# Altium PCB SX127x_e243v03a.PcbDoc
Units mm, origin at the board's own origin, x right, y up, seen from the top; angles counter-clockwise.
Board outline 56 x 36 mm, 2 copper layers (Top Layer, Bottom Layer), stack 1.6 mm thick; 60 components, 66 nets, 205 pads, 400 vias.
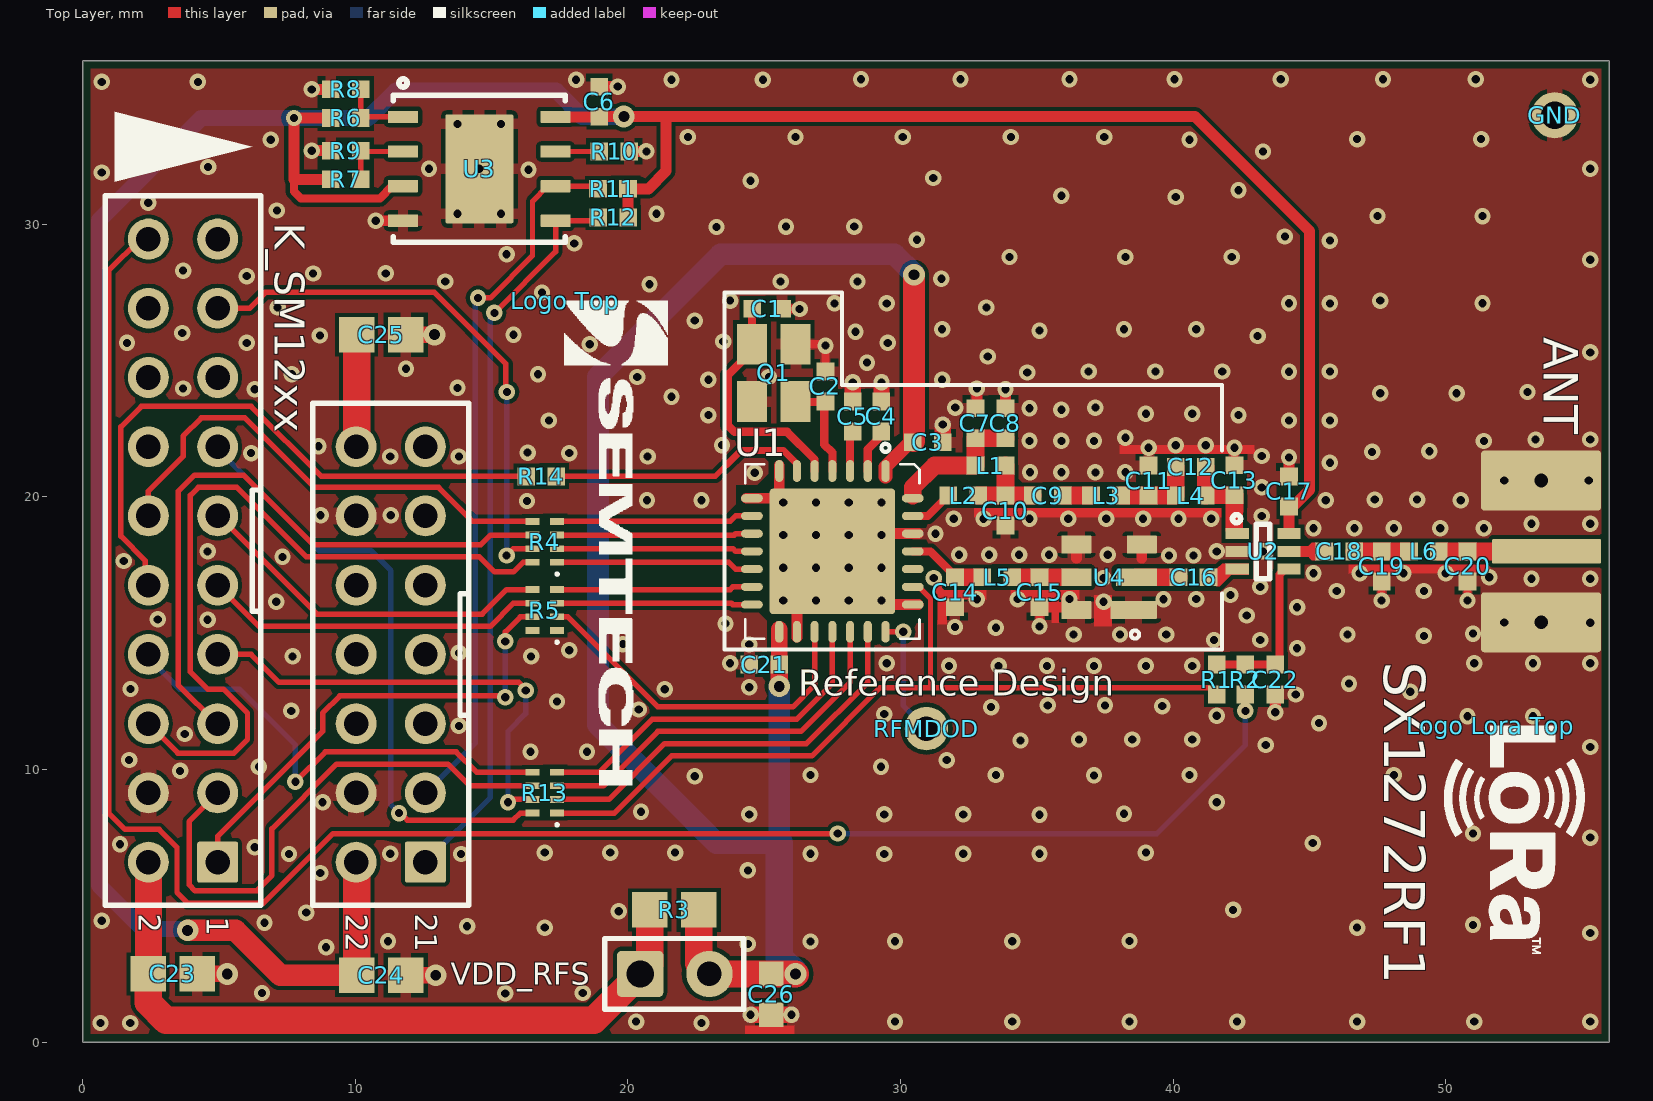
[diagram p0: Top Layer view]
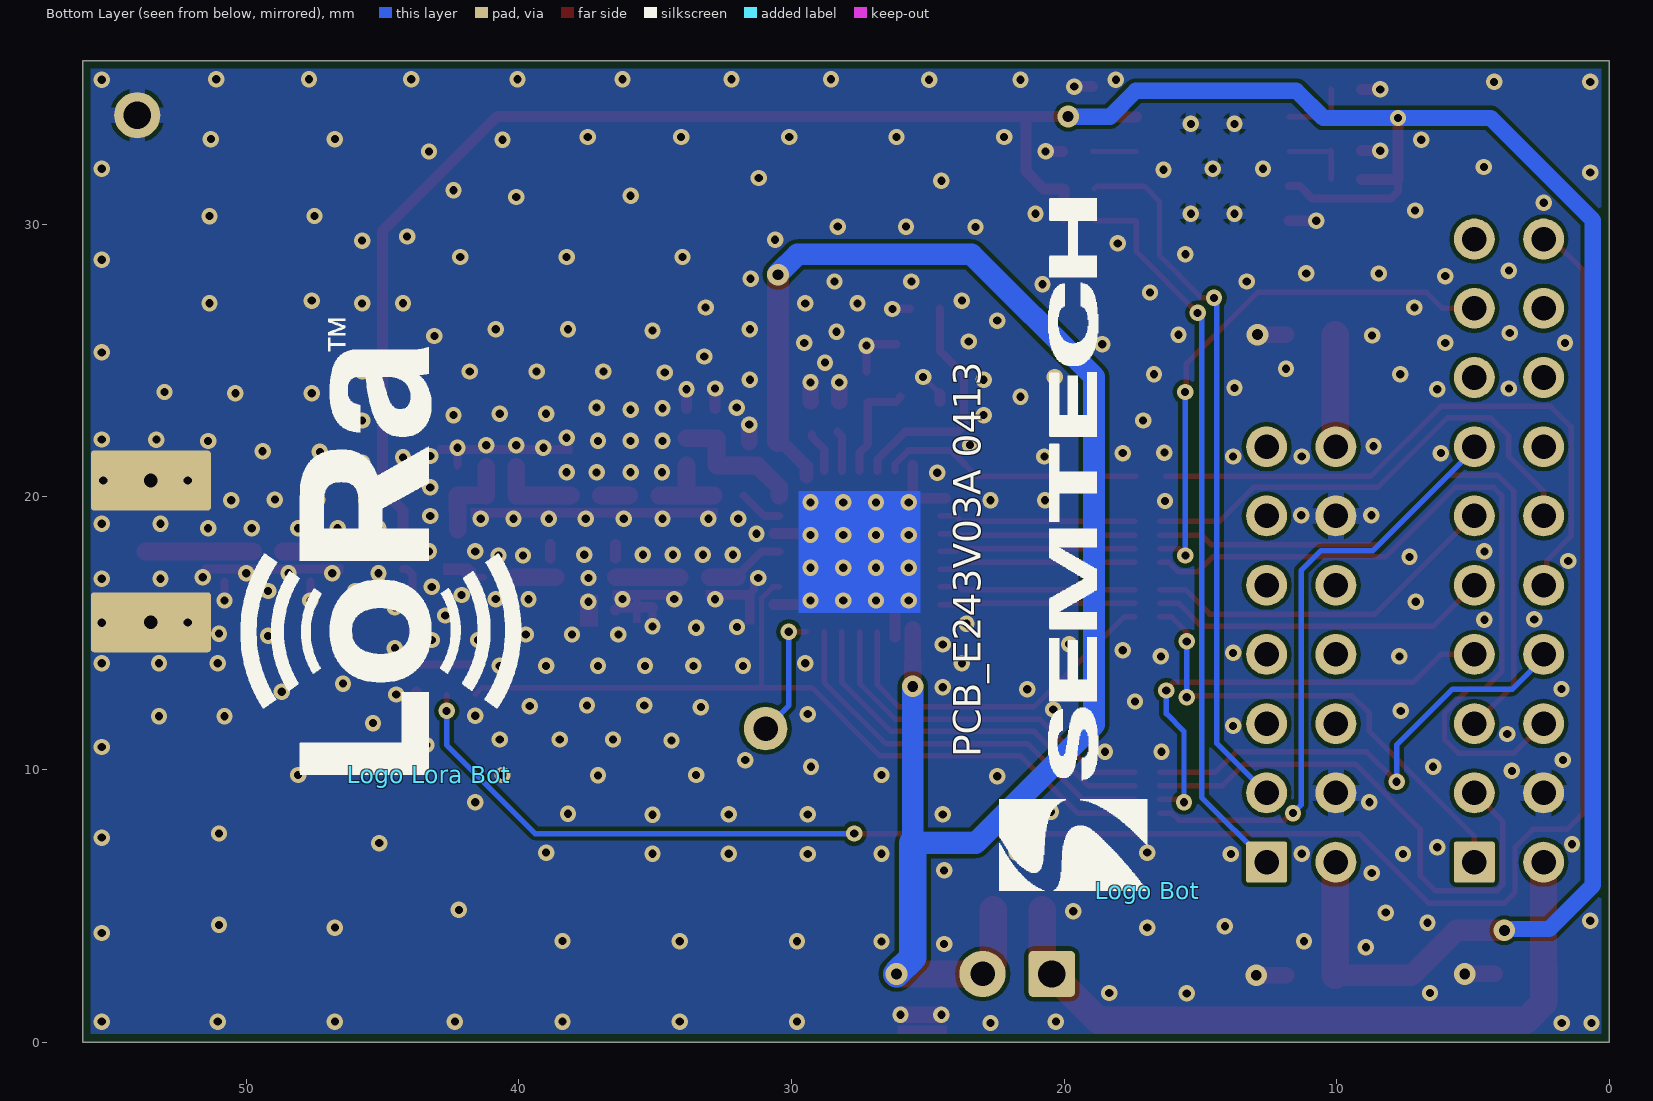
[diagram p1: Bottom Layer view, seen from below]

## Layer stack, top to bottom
Top Layer: signal copper 0.035
Dielectric: core 1.53, FR-4, Dk 4.2
Bottom Layer: signal copper 0.035

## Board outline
0,0 0,36 56,36 56,0

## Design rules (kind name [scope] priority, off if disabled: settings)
Clearance Clearance_GND [InNet('GND')] p1: gap=0.15
Clearance [All] p2: gap=0.15
ComponentClearance ComponentClearance_keepout ['SX1232LR_e243v01a' vs OnLayer('Mechanical 12')] p1: gap=0.25 collisioncheckmode=3 verticalgap=0.3 showdistances=FALSE
ComponentClearance [All] p2: gap=0.25 collisioncheckmode=3 verticalgap=0.3 showdistances=FALSE
HoleSize [All] p1: absolutevalues=TRUE maxlimit=3.6 minlimit=0.25 maxpercent=80.000 minpercent=20.000
HoleToHoleClearance [All] p1: gap=0.25 allowstackedmicrovias=TRUE
MinimumSolderMaskSliver [All] p1: minsoldermaskwidth=0.05
PlaneClearance [All] p1: clearance=0.2
PlaneConnect [All] p1: planeconnectstyle=Direct reliefexpansion=0.508 reliefentries=4 reliefconductorwidth=0.254 reliefairgap=0.254
PolygonConnect "PolygonConnect SAW_DCC6C" [InNet('GND') vs HasFootprint('DCC6C_3.0x3.0mm')] p1: connectstyle=Relief reliefconductorwidth=0.65 reliefentries=4 polygonreliefangle="90 Angle"
PolygonConnect "PolygonConnect SMD" [InNet('GND') vs HasFootprint('nd3225da - nd2520da') or HasFootprint('DD10_L') or HasFootprint('MSOP8')  or  HasFootprint('vqfn28_6x6mm') or HasFootprint('SOIC-SN8_L')  or HasFootprint('rlc_1206_smd capa pol') or HasFootprint('rlc_603_smd') or HasFootprint('rlc_402_smd') or HasFootprint('rlc_402_smd diode') or hasFootprint('rlc_805_smd') or HasFootprint('rlc_1210_smd')   or HasFootprint('MiniMold-6') or HasFootprint('DFN8_ 5x6mm')] p2: connectstyle=Relief reliefconductorwidth=0.4 reliefentries=4 polygonreliefangle="90 Angle"
PolygonConnect PolygonConnect_comp_diverse [InNet('GND') vs HasFootprint('CD1608-0603') or  HasFootprint('HDR34 Header') or  HasFootprint('BRIDGE_254MM') or  HasFootprint('pin_1mm') or HasFootprint('SMA_END_LAUNCH_JACK_RECEPTACLE')] p3: connectstyle=Relief reliefconductorwidth=0.6 reliefentries=4 polygonreliefangle="90 Angle"
PolygonConnect PolygonConnect_all [All] p4: connectstyle=Direct reliefconductorwidth=0.6 reliefentries=4 polygonreliefangle="90 Angle"
RoomDefinition SX127x_e243v03a [InComponentClass('SX127x_e243v03a')] p1: confinementstyle=ConfineOut formatcopy=TRUE lockcomponents=FALSE outline 62.449,-0.9 62.449,6.1 67.709,6.1 67.709,-0.9
RoutingVias [All] p1: holewidth=0.3 width=0.6 viastyle="Through Hole" minholewidth=0.25 minwidth=0.5 maxholewidth=0.4 maxwidth=0.8
SilkToSilkClearance [All] p1: silktosilkclearance=0.05
SilkscreenOverComponentPads [All] p1: minsilkscreentomaskgap=0.05
SolderMaskExpansion [All] p1: expansion=0.05
Width "Width GND" [InNet('GND')] p1: maxlimit=3 minlimit=0.2 preferedwidth=0.4
Width Width_VCC [InNet('VDD_RF') or  InNet('VDD_RFS') or  InNet('VCC') or  InNet('VBAT') or InNet('VSUPERCAP') or InNet('VCC_FEM')   or InNet('VCC_PA')] p2: maxlimit=2 minlimit=0.2 preferedwidth=0.8
Width "Width All" [All] p3: maxlimit=2 minlimit=0.15 preferedwidth=0.2
20 further rules are at their usual default settings.

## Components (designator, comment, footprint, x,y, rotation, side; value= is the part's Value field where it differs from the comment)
ANT "SMA" "SMA END LAUNCH JACK RECEPTACLE SHORT" 53.7,18 r90 top locked
C1 "Cap" rlc_402_smd 25.11,26.904 r180 top
C2 "Cap" rlc_402_smd 27.248,24.05 r270 top
C3 "Cap" rlc_402_smd 31,22 r180 top
C4 "Cap" rlc_402_smd 29.295,22.95 r270 top
C5 "Cap" rlc_402_smd 28.25,22.95 r270 top
C6 "Cap" rlc_402_smd 18.949,34.5 r270 top
C7 "Cap" rlc_402_smd 32.75,22.7 r270 top
C8 "Cap" rlc_402_smd 33.85,22.7 r270 top
C9 "Cap" rlc_402_smd 35.4,20.05 r180 top
C10 "Cap" rlc_402_smd 33.85,19.5 r90 top
C11 "Cap" rlc_402_smd 39.1,20.6 r270 top
C12 "Cap" rlc_402_smd 40.65,21.1 r180 top
C13 "Cap" rlc_402_smd 42.249,20.61 r270 top
C14 "Cap" rlc_402_smd 32,16.5 r90 top
C15 "Cap" rlc_402_smd 35.1,16.5 r90 top
C16 "Cap" rlc_402_smd 40.75,17.05 r180 top
C17 "Cap" rlc_402_smd 44.252,20.2 r270 top
C18 "Cap" rlc_402_smd 46.1,18 r180 top
C19 "Cap" rlc_402_smd 47.65,17.45 r90 top
C20 "Cap" rlc_402_smd 50.8,17.45 r90 top
C21 "Cap" rlc_402_smd 25,13.85 r0 top
C22 "Cap" rlc_402_smd 43.749,13.3 r270 top
C23 "Cap" rlc_805_smd 3.299,2.5 r180 top
C24 "Cap" rlc_805_smd 10.949,2.45 r180 top
C25 "Cap" rlc_805_smd 10.949,25.95 r0 top
C26 "Cap Semi" rlc_603_smd 25.25,1.75 r90 top
GND "Test Pin" pin_1mm 54,34 r0 top
K_SM12xx "SM12xx Header" "HDR34 Header" 4.95,6.6 r90 top locked
L1 "Inductor" rlc_402_smd 33.3,21.15 r180 top
L2 "Inductor" rlc_402_smd 32.3,20.05 r0 top
L3 "Inductor" rlc_402_smd 37.54,20.05 r0 top
L4 "Inductor" rlc_402_smd 40.65,20.05 r0 top
L5 "Inductor" rlc_402_smd 33.55,17.05 r0 top
L6 "Inductor" rlc_402_smd 49.2,18 r0 top
"Logo Bot" "Logo symbol" logo_semtech_horiz_size3 16.95,5.55 r90 bottom
"Logo Lora Bot" "Logo symbol" "Logo LoRa Size4" 43.3,9.8 r90 bottom
"Logo Lora Top" "Logo symbol" "Logo LoRa Size2" 51.65,11.6 r270 top
"Logo Top" "Logo symbol" logo_semtech_horiz_size2 17.7,27.2 r270 top
Q1 "Xtal" "ND3225DA - ND2520DA" 25.35,24.551 r270 top
R1 "Resistor" rlc_402_smd 41.6,13.3 r90 top
R2 "Resistor" rlc_402_smd 42.649,13.3 r270 top
R3 "Resistor" rlc_805_smd 21.7,4.85 r180 top
R4 "EXBN8VxxxJX" EXB28V 16.95,18.35 r90 top
R5 "EXBN8VxxxJX" EXB28V 16.95,15.85 r90 top
R6 "Resistor" rlc_402_smd 9.649,33.9 r180 top
R7 "Resistor" rlc_402_smd 9.649,31.65 r180 top
R8 "Resistor" rlc_402_smd 9.649,34.95 r0 top
R9 "Resistor" rlc_402_smd 9.649,32.7 r0 top
R10 "Resistor" rlc_402_smd 19.499,32.674 r180 top
R11 "Resistor" rlc_402_smd 19.45,31.3 r0 top
R12 "Resistor" rlc_402_smd 19.457,30.25 r0 top
R13 "EXBN8VxxxJX" EXB28V 16.95,9.15 r90 top
R14 "Resistor" rlc_402_smd 16.821,20.75 r180 top
RFMDOD "Test Pin" pin_0.9mm 30.95,12 r90 top
U1 "SX1272" vqfn28_6x6mm 27.5,18 r270 top
U2 "RF Switch" SC70-6 43.3,18 r0 top
U3 "24AA128-I/MF" "DFN8_ 5x6mm" 14.549,32.035 r270 top
U4 "SAW Filter" DCC6C_3.0X3.0MM 37.65,17.05 r180 top
VDD_RFS "Jumper" BRIDGE_254MM 20.45,2.5 r0 top

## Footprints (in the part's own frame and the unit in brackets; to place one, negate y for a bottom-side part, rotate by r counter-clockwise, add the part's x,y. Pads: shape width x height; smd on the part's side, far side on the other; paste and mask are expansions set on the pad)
BRIDGE_254MM [mm] "Generic Bridge 2.54mm, 2 Leads 0.9mm;"
  rrect20% 1.7x1.7 hole 1 paste+0 mask+0.05: 1(0,0)
  round 1.7 hole 0.9 paste+0 mask+0.05: 2(2.54,0)
  silkscreen extent -1.3,-1.3 3.8,1.3, body extent -1.4,-1.4 3.9,1.4, height 1
DCC6C_3.0X3.0MM [mm] "DCC6C footprint, 3.0x3.0mm"
  rrect5% 1.7x0.65 smd mask+0.05: 1(-0.9,1.2)
  rrect5% 1.5x0.65 smd mask+0.05: 2(-1,0)
  rrect5% 1.1x0.65 smd mask+0.05: 3(-1.2,-1.2) 4(1.2,-1.2) 5(1.2,0) 6(1.2,1.2)
  silkscreen extent -1.1,1.95 -0.8,2.25, body extent -1.5,-1.5 1.5,1.5, height 1
"DFN8_ 5x6mm" [mm] "8 Leads, Body 5x6mm, pitch 1.27mm, DFN8"
  rrect10% 0.45x1.1 smd paste+0 mask+0.05: 1(-1.905,-2.8) 2(-0.635,-2.8) 3(0.635,-2.8) 4(1.905,-2.8) 5(1.905,2.8) 6(0.635,2.8) 7(-0.635,2.8) 8(-1.905,2.8)
  rrect5% 4x2.5 smd paste+0 mask+0.05: 9(0,0)
  silkscreen extent -3.3,-3.15 2.7,3.15, body extent -2.5,-3 2.5,3, height 12
EXB28V [mm] "Chip Resistor Array, (0402x4); SM; 8 Leads; Body 2.10 x 1.10 mm (LxW max)"
  rect 0.25x0.5 smd: 1(-0.75,-0.45) 2(-0.25,-0.45) 3(0.25,-0.45) 4(0.75,-0.45) 5(0.75,0.45) 6(0.25,0.45) 7(-0.25,0.45) 8(-0.75,0.45)
  silkscreen extent -1.23,-0.5 -1.13,-0.4
"HDR34 Header" [mm] "Connector; Header; 34 Position - SM12xx Header"
  rrect10% 1.5x1.5 hole 0.9 mask+0.05: 1(0,0) 21(0,-7.62)
  round 1.5 hole 0.9 mask+0.05: 2(0,2.54) 3(2.54,0) 4(2.54,2.54) 5(5.08,0) 6(5.08,2.54) 7(7.62,0) 8(7.62,2.54) 9(10.16,0) 10(10.16,2.54) 11(12.7,0) 12(12.7,2.54) 13(15.24,0) 14(15.24,2.54) 15(17.78,0) 16(17.78,2.54) 17(20.32,0) 18(20.32,2.54) 19(22.86,0) 20(22.86,2.54) 22(0,-5.08) 23(2.54,-7.62) 24(2.54,-5.08) 25(5.08,-7.62) 26(5.08,-5.08) 27(7.62,-7.62) 28(7.62,-5.08) 29(10.16,-7.62) 30(10.16,-5.08) 31(12.7,-7.62) 32(12.7,-5.08) 33(15.24,-7.62) 34(15.24,-5.08)
  silkscreen extent -1.59,-9.21 27.53,4.13, body extent -1.59,-9.21 24.45,4.13
"Logo LoRa Size2" [mm]
  silkscreen extent 0,-1.69 8.37,3.44
"Logo LoRa Size4" [mm] "Logo LoRa Size4 - Top Overlay"
  silkscreen extent 0,-3.38 16.73,6.89
logo_semtech_horiz_size2 [mm] "Logo semtech horizontal - size2 - M"
  silkscreen extent 0,-0.03 17.78,3.76, body extent 0,0 0.08,0, height 6
logo_semtech_horiz_size3 [mm] "Logo semtech horizontal - size3 - L"
  silkscreen extent 0,0 25.4,5.41, body extent -0.01,-0.01 25.41,5.42
"ND3225DA - ND2520DA" [mm] "Crystal SMD 3.2x2.5mm compatible with 2.5x2.0mm"
  rect 1.5x1.1 smd mask+0.05: 1(-1.05,-0.8) 2(1.05,-0.8) 3(1.05,0.8) 4(-1.05,0.8)
  body extent -1.6,-1.25 1.6,1.25, height 1
pin_0.9mm [mm] "Generic Pin 0.9mm; 1 Lead"
  round 1.6 hole 0.9 mask+0.05: 1(-0.5,0)
pin_1mm [mm] "Generic Pin 1.1mm; 1 Lead"
  round 1.7 hole 1 paste+0 mask+0.05: 1(0,0)
rlc_402_smd [mm] "Chip SMD component 402; Body 1.0 x 0.5 mm (LxW typ)"
  rect 0.65x0.65 smd mask+0.05: 1(-0.55,0) 2(0.55,0)
rlc_603_smd [mm] "Chip SMD component 603; Body 1.6 x 0.8mm (LxW typ)"
  rect 0.9x0.9 smd paste+0 mask+0.05: 1(-0.75,0) 2(0.75,0)
rlc_805_smd [mm] "Chip SMD component 805; Body 2.0 x 1.25 mm (LxW typ)"
  rect 1.3x1.3 smd mask+0.05: 1(-0.9,0) 2(0.9,0)
SC70-6 [mm] "SC70 6-Leads, Body 2.0x1.25mm, Pitch 0.65mm"
  rect 0.85x0.4 smd mask+0.05: 1(-0.95,0.65) 2(-0.95,0) 3(-0.95,-0.65) 4(0.95,-0.65) 5(0.95,0) 6(0.95,0.65)
  silkscreen extent -1.12,-1 0.25,1.35, body extent -0.63,-1 0.63,1, height 1.45
"SMA END LAUNCH JACK RECEPTACLE SHORT" [mm] "SMA Connector - End Launch Jack Receptacle - Short"
  rrect10% 0.9x4 smd paste+0 mask+0.05: 1(0,0)
  rrect10% 2.2x4.4 hole 0.5 mask+0.05: 2(-2.6,0.2) 2(2.6,0.2)
  body extent -0.5,-2.05 0.5,2.05, height 8
vqfn28_6x6mm [mm] "28 Leads, Body 6.0x6.0mm, Pitch 0.65mm, VQFN28"
  oval 0.8x0.3 smd mask+0.05: 1(-2.95,1.95) 2(-2.95,1.3) 3(-2.95,0.65) 4(-2.95,0) 5(-2.95,-0.65) 6(-2.95,-1.3) 7(-2.95,-1.95) 15(2.95,-1.95) 16(2.95,-1.3) 17(2.95,-0.65) 18(2.95,0) 19(2.95,0.65) 20(2.95,1.3) 21(2.95,1.95)
  oval 0.3x0.8 smd mask+0.05: 8(-1.95,-2.95) 9(-1.3,-2.95) 10(-0.65,-2.95) 11(0,-2.95) 12(0.65,-2.95) 13(1.3,-2.95) 14(1.95,-2.95) 22(1.95,2.95) 23(1.3,2.95) 24(0.65,2.95) 25(0,2.95) 26(-0.65,2.95) 27(-1.3,2.95) 28(-1.95,2.95)
  rrect5% 4.6x4.6 smd paste-3.3 mask+0.05: 29(0,0)
  Mechanical 15 keep-out lines w0.1: 3.5,-3.5 3.5,3.5 -3.5,3.5 -3.5,-3.5 3.5,-3.5
  silkscreen extent -3.95,-3.2 3.2,3.2, body extent -3,-3 3,3, height 1

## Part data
ANT: "SMA Straight Connector"
C1 C2 C3 C4 C5 C6 C7 C8 C9 C10 C11 C12 C13 C14 C15 C16 C17 C18 C19 C20 C21 C22 C23 C24 C25: "Capacitor SMD"
C26: "Capacitor (Semiconductor SIM Model)"
GND RFMDOD: library part test_pin
K_SM12xx: "SM12xx Header; 34pins: 2x10pins + 2x7pins"
L1 L2 L3 L4 L5 L6: "Inductor SMD"
"Logo Bot" "Logo Lora Bot" "Logo Lora Top" "Logo Top": library part Logo, "Schematic symbol for Logo"
Q1: library part "Xtal GND", "Crystal with GND pins"
R1 R2 R3 R6 R7 R8 R9 R10 R11 R12 R14: "Resistor SMD - IEC symbol version"
R4 R5 R13: "Mini-Flat Package, Isolated Resistor Network, 0.031 W/resistor"
U1: "SX1272 - Low Power Integrated UHF Transceiver with Lora technology"
U2: library part "PE4259 RF Switch", "PE4259 Peregrine RF Switch"
U3: "128kbit, 400kHz, 1.7V, 8-Pin DFN, Industrial Temperature"
U4: "SAW Filter - Bandpass - TEMEX type"
VDD_RFS: "Jumper Wire"

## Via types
v1: diameter 0.6, hole 0.3, Top Layer to Bottom Layer, tented both sides, 370 vias
v2: diameter 0.6, hole 0.3, Top Layer to Bottom Layer, tented top, 21 vias
v3: diameter 0.8, hole 0.4, Top Layer to Bottom Layer, tented both sides, 8 vias
v4: diameter 0.58, hole 0.3, Top Layer to Bottom Layer, tented both sides, 1 vias

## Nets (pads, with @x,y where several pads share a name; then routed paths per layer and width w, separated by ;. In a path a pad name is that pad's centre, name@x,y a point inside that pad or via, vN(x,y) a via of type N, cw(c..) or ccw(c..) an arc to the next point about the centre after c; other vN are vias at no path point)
DIO0: K_SM12xx.12 R4.5 | length 18.1
  Top Layer w0.2: K_SM12xx.12 2.41,20.21 3.683,21.483 3.683,22.233 4.35,22.9 5.95,22.9 8.5,20.35 13.056,20.35 14.306,19.1 R4.5
DIO0_SX: R4.4 U1.9 | length 7.2
  Top Layer w0.2: R4.4 23.75,19.1 23.95,19.3 U1.9
DIO1: K_SM12xx.5 R4.6 | length 23.6
  Top Layer w0.2: K_SM12xx.5 4.92,11.68 3.5,13.1 3.5,20.2 4.1,20.8 5.9,20.8 8.45,18.25 14.611,18.25 14.961,18.6 R4.6
DIO1_SX: R4.3 U1.10 | length 7.2
  Top Layer w0.2: R4.3 23.9,18.6 23.95,18.65 U1.10
DIO2: K_SM12xx.17 R4.7 | length 20
  Top Layer w0.2: K_SM12xx.17 6.12,26.92 6.7,27.5 12.9,27.5 15.524,24.876 15.524,23.885 v1(15.559,23.85) ; v1(15.55,17.85) 15.8,18.1 R4.7
  Bottom Layer w0.2: v1(15.55,17.85) 15.55,23.841 v1(15.559,23.85)
DIO2_SX: R4.2 U1.11 | length 7.2
  Top Layer w0.2: R4.2 23.85,18.1 23.95,18 U1.11
DIO3: K_SM12xx.6 R4.8 | length 28.6
  Top Layer w0.2: K_SM12xx.6 3.49,10.6 5.54,10.6 6.045,11.105 6.045,12.068 5.163,12.95 4.58,12.95 3.95,13.58 3.95,20.06 4.24,20.35 5.65,20.35 8.2,17.8 14.556,17.8 15.106,17.25 15.8,17.25 16.15,17.6 R4.8
DIO3_SX: R4.1 U1.12 | length 7.3
  Top Layer w0.2: R4.1 23.7,17.6 23.95,17.35 U1.12
DIO4: K_SM12xx.11 R5.5 | length 13.4
  Top Layer w0.2: K_SM12xx.11 5,19.3 8.6,15.7 14.65,15.7 15.55,16.6 R5.5
DIO4_SX: R5.4 U1.13 | length 7.2
  Top Layer w0.2: R5.4 23.75,16.6 23.85,16.7 U1.13
DIO5: K_SM12xx.9 R5.6 | length 12.5
  Top Layer w0.2: K_SM12xx.9 6.46,15.25 14.951,15.25 15.801,16.1 R5.6
DIO5_SX: R5.3 U1.14 | length 7.2
  Top Layer w0.2: R5.3 23.8,16.1 23.85,16.05 U1.14
FEM_ANT_SEL: K_SM12xx.16
FEM_CPS: K_SM12xx.18
FEM_CSD: K_SM12xx.19
FEM_CTX: K_SM12xx.20 R2.2 | length 70.1
  Top Layer w0.2: K_SM12xx.20 2.11,29.46 0.95,28.3 0.95,8.405 1.555,7.8 2.8,7.8 3.458,7.142 3.458,5.492 3.85,5.1 6.63,5.1 9.18,7.65 v1(27.7,7.65) ; v1@42.649,12.151 R2.2
  Bottom Layer w0.2: v1(27.7,7.65) 39.4,7.65 42.649,10.899 v1(42.65,12.15)
FEM_SPARE: K_SM12xx.14
GND: ANT.2 C1.1 C2.1 C3.1 C4.1 C5.1 C6.1 C7.1 C8.1 C10.1 C11.1 C13.1 C14.1 C15.1 C17.1 C19.1 C20.1 C21.1 C22.2 C23.1 C24.1 C25.2 C26.1 GND.1 K_SM12xx.4 K_SM12xx.24 K_SM12xx.32 Q1.2 Q1.4 R8.1 R9.1 R10.1 U1.7 U1.8 U1.16 U1.22 U1.26 U1.29 U2.2 U3.4 U3.9 U4.1 U4.3 U4.4 U4.6 | length 39.2
  Top Layer w0.2: Q1.2@24.55,23.78 v1(25.17,24.4)
  Top Layer w0.3: U1.29@25.55,19.95 U1.29 ; C1.1 26.29,26.904 v1(26.3,26.894) ; Q1.4 v1@27.248,25.601 ; C2.1 v1(27.248,25.55) ; v1(31.216,17.024) 31.375,16.866 31.375,16.601 31.551,16.425 31.602,16.425 ; v1@32.8,23.85 v1@32.8,23.95 ; v1(35.1,15.25) C15.1 ; C13.1 v1@42.249,21.731 ; v1(47.65,16.199) C19.1@47.65,16.899 ; v1(50.8,16.199) C20.1@50.8,16.899
  Top Layer w0.4: v1(8.4,32.7) R9.1 ; v1(8.4,34.95) R8.1 ; v1(10.75,30.13) U3.4 ; C6.1 v1(19.63,35.05) ; R10.1 v1(20.676,32.674) ; U1.8@24.35,19.95 U1.8 25.55,19.95 U1.7@25.55,21.15 ; Q1.2 Q1.2@24.55,23.78 ; U1.16@26.2,14.85 26.2,16.7 U1.29 ; U1.22@30.65,16.05 U1.22 29.45,16.05 U1.29 ; U1.26@30.65,18.65 U1.26 28.15,18.65 U1.29 ; C7.1@32.8,23.25 v1@32.8,23.85 ; C8.1 v1@33.85,23.85 ; C15.1 36.35,15.95 U4.6 ; 36.45,17.75 U4.4 ; 38.85,17.75 U4.3 ; C22.2@43.749,12.85 C22.2 43.75,12.16 v1(43.75,12.1) ; v1(44.25,21.45) 44.25,21.415 44.252,21.413 C17.1
  Top Layer w0.6: C23.1 v3(5.3,2.5) ; C24.1 v3(12.95,2.45) ; C25.2 v3(12.9,25.95) ; v1(24.5,1) C26.1 v1(26,1) ; C5.1 v1(28.25,24.201) ; C4.1 29.3,23.505 v1(29.3,24.201) ; C3.1 v1(31.55,22.65)
  other v1: 0.65,0.7 1.744,0.7 22.7,0.7 20.3,0.75 29.8,0.75 34.1,0.75 38.4,0.75 42.349,0.75 46.75,0.75 51.05,0.75 55.3,0.75 6.574,1.8 15.5,1.787 18.34,1.8 8.929,3.481 24.4,3.6 11.2,3.7 26.7,3.691 29.8,3.7 34.1,3.7 38.4,3.708 55.3,4 16.95,4.2 46.75,4.2 14.1,4.25 51,4.3 6.667,4.377 0.7,4.45 8.2,4.75 19.66,4.8 42.2,4.85 8.714,6.2 24.4,6.3 7.567,6.9 11.28,6.908 13.88,6.9 26.7,6.908 29.4,6.9 32.3,6.908 35.1,6.908 16.95,6.95 19.355,6.95 21.73,6.95 39,6.95 6.31,7.15 1.367,7.259 45.125,7.3 55.3,7.5 51,7.65 24.45,8.354 29.4,8.354 32.3,8.354 35.1,8.341 38.2,8.376 20.481,8.45 8.8,8.8 41.6,8.8 22.45,9.75 37.1,9.782 26.7,9.8 33.5,9.8 40.6,9.8 48.1,9.8 3.573,9.95 6.461,10.1 29.285,10.1 1.7,10.35 31.698,10.345 16.426,10.65 18.5,10.65 55.3,10.822 43.4,10.899 34.4,11.062 36.55,11.1 38.5,11.1 40.7,11.1 3.74,11.3 13.798,11.6 45.35,11.7 50.8,11.95 53.2,11.95 41.6,11.97 29.4,12.03 7.65,12.15 20.4,12.2 33.325,12.288 39.6,12.326 35.4,12.35 37.5,12.35 17.396,12.494 44.5,12.75 48.7,12.85 1.75,12.95 21.35,12.945 24.45,13.02 46.45,13.15 31.78,13.8 33.6,13.8 35.375,13.8 37.1,13.8 39,13.8 40.7,13.8 23.75,13.9 29.495,13.9 51.05,13.9 53.2,13.9 55.3,13.9 7.7,14.15 16.45,14.15 13.798,14.276 17.85,14.375 44.55,14.45 24.45,14.584 19.815,14.6 41.5,14.75 43.2,14.75 49.2,14.9 36.35,14.95 38.053,14.953 39.75,14.95 46.4,14.95 51,14.983 33.5,15.2 31.998,15.226 23.578,15.35 52.15,15.392 55.3,15.385 4.58,15.49 2.75,15.505 42.7,15.65 44.55,15.95 7.1,16.15 37.45,16.15 32.8,16.245 34.3,16.25 36.2,16.25 39.65,16.245 40.85,16.25 42.1,16.4 46,16.55 49.2,16.55 43.2,16.7 53.15,17 55.3,17 51.6,17.05 45.15,17.2 46.85,17.2 48.45,17.2 50,17.2 1.502,17.65 7.326,17.8 39.85,17.85 40.75,17.85 32.15,17.876 33.25,17.876 34.35,17.876 35.45,17.876 37.6,17.876 4.58,18 41.6,18 43.3,18 31.283,18.65 45.15,18.85 46.65,18.85 48.1,18.85 49.8,18.85 51.4,18.85 53.15,19.017 55.3,19.017 31.95,19.2 33.05,19.2 34.73,19.2 36.15,19.2 37.55,19.2 38.9,19.2 40.2,19.2 41.4,19.2 43.25,19.3 8.725,19.325 11.3,19.325 16.3,19.85 20.7,19.875 22.7,19.875 45.6,19.875 50.55,19.875 47.4,19.9 48.95,19.9 43.25,20.35 52.15,20.6 55.25,20.6 24.656,20.885 34.75,20.905 35.9,20.905 37.15,20.9 38.25,20.905 45.75,21.25 11.28,21.483 13.8,21.483 20.724,21.483 43.25,21.5 6.178,21.605 17.85,21.605 16.32,21.625 47.3,21.65 49.4,21.675 39.1,21.8 42.249,21.8 8.65,21.859 40.1,21.895 41.2,21.895 23.45,21.9 51.4,22.05 34.73,22.054 35.9,22.054 37.1,22.054 53.3,22.1 55.3,22.104 38.25,22.171 17.1,22.8 44.25,22.8 45.75,22.8 22.95,23 42.4,23 39,23.05 40.7,23.05 35.9,23.2 34.73,23.25 32.008,23.275 37.15,23.275 21.6,23.672 47.6,23.8 50.4,23.8 53,23.85 6.31,23.95 33.85,23.95 3.683,23.975 32.8,23.975 13.749,24 22.95,24.3 31.525,24.3 20.342,24.4 7.666,24.5 16.7,24.5 34.65,24.562 44.25,24.589 36.9,24.6 39.35,24.6 41.8,24.6 45.75,24.6 11.861,24.7 28.772,24.925 33.2,25.15 55.3,25.3 18.6,25.6 1.625,25.65 6.014,25.65 29.533,25.65 23.5,25.7 43.1,25.9 8.7,25.92 15.801,25.95 3.652,26.012 28.35,26.055 35.1,26.1 31.525,26.15 38.2,26.15 40.85,26.15 22.45,26.466 7.15,26.95 33.15,26.95 27.58,27.1 29.495,27.1 44.25,27.104 45.75,27.1 51.35,27.104 23.75,27.2 47.6,27.2 16.85,27.5 20.79,27.8 13.3,27.9 25.6,27.9 28.424,27.9 31.5,28 6.014,28.1 8.45,28.194 11.116,28.2 3.683,28.3 55.3,28.7 34,28.8 38.25,28.8 42.15,28.8 15.549,28.9 18.029,29.3 45.75,29.4 30.6,29.436 44.1,29.55 23.25,29.9 25.8,29.914 28.3,29.914 47.5,30.302 51.35,30.3 21.05,30.385 7.122,30.508 2.4,30.793 40.1,31 35.9,31.05 42.4,31.25 24.5,31.6 31.198,31.7 0.7,31.9 16.35,32 12.7,32.035 55.3,32.035 4.6,32.1 43.3,32.67 6.9,33.1 40.6,33.1 46.75,33.127 51.3,33.127 22.2,33.2 26.15,33.2 30.083,33.2 34.05,33.2 37.475,33.2 0.7,35.224 4.225,35.224 18.1,35.3 21.6,35.3 24.95,35.3 55.3,35.3 28.55,35.324 32.2,35.324 36.2,35.324 40.053,35.324 43.949,35.324 47.7,35.324 51.1,35.324
  other v2: 25.7,16.2 26.9,16.2 28.1,16.2 29.3,16.2 25.7,17.4 26.9,17.4 28.1,17.4 29.3,17.4 25.7,18.6 26.9,18.6 28.1,18.6 29.3,18.6 25.7,19.8 26.9,19.8 28.1,19.8 29.3,19.8 13.749,30.385 15.349,30.385 14.549,32.035 13.749,33.685 15.349,33.685
  other v4: 37.45,17.025
MISO: K_SM12xx.8 R13.5 | length 17.7
  Top Layer w0.2: v1(7.8,9.55) 8.9,10.65 13.7,10.65 14.45,9.9 R13.5
  Bottom Layer w0.2: K_SM12xx.8 2.41,14.09 3.55,12.95 5.75,12.95 7.8,10.9 v1(7.8,9.55)
MISO_SX: R13.4 U1.18 | length 13.3
  Top Layer w0.2: R13.4 18.95,9.9 20.9,11.85 26.2,11.85 27.5,13.15 U1.18
MOSI: K_SM12xx.3 R13.6 | length 19.8
  Top Layer w0.2: K_SM12xx.3 3.9,8.09 3.9,5.773 4.123,5.55 6.379,5.55 6.939,6.111 6.939,7.822 9.317,10.2 13.4,10.2 14.2,9.4 R13.6
MOSI_SX: R13.3 U1.19 | length 14.2
  Top Layer w0.2: R13.3 19.1,9.4 21.1,11.4 26.35,11.4 28.15,13.2 28.15,14.45 U1.19@28.15,15.05
NetANT_1: ANT.1 C20.2 L6.2 | length 4
  Top Layer w0.65: L6.2 C20.2 ANT.1
NetC1_2: C1.2 Q1.1 U1.5 | length 8.8
  Top Layer w0.3: C1.2 24.55,26.894 Q1.1 24.55,25.35 23.672,24.472 23.672,22.62 23.905,22.387 25.843,22.387 26.85,21.38 U1.5
NetC2_2: C2.2 Q1.3 U1.4 | length 3.7
  Top Layer w0.3: Q1.3@26,23.672 Q1.3@26.008,23.68 ; Q1.3 26.17,23.481 27.2,23.481 27.2,21.925 27.5,21.625 U1.4
NetC4_2: C4.2 U1.2 | length 1.5
  Top Layer w0.3: U1.2 28.8,21.75 29.25,22.2 C4.2@29.25,22.3
NetC5_2: C5.2 U1.3 | length 1.5
  Top Layer w0.3: U1.3@28.15,20.95 28.15,22.225 C5.2@28.312,22.387
NetC7_2: C7.2 C8.2 L1.2 U1.28 | length 5
  Top Layer w0.65: U1.28@30.45,20.05 30.45,20.35 31.25,21.15 L1.2 C7.2 C8.2
NetC9_1: C9.1 L3.1 | length 1
  Top Layer w0.65: C9.1 L3.1
NetC9_2: C9.2 C10.2 L1.1 L2.2 | length 3.1
  Top Layer w0.65: L2.2 C10.2 ; L1.1 C10.2 ; C9.2 C10.2
NetC11_2: C11.2 C12.2 L3.2 L4.1 | length 3.1
  Top Layer w0.65: L3.2 C11.2 L4.1 C12.2
NetC12_1: C12.1 C13.2 L4.2 U2.1 | length 3.4
  Top Layer w0.65: C12.1 L4.2 41.21,20.06 C13.2 U2.1@42.243,18.8
NetC14_2: C14.2 L5.1 U1.25 | length 3
  Top Layer w0.3: U1.25 31.1,18 32,17.1 C14.2
  Top Layer w0.65: C14.2 L5.1
NetC15_2: C15.2 L5.2 U4.5 | length 2.4
  Top Layer w0.65: L5.2 C15.2 U4.5
NetC16_1: C16.1 U2.3 | length 1.2
  Top Layer w0.25: C16.1 41.85,17.05 42.15,17.35 U2.3
NetC16_2: C16.2 U4.2 | length 1.5
  Top Layer w0.65: U4.2 C16.2
NetC18_1: C18.1 C19.2 L6.1 | length 2
  Top Layer w0.65: C18.1 C19.2 L6.1
NetC18_2: C18.2 U2.5 | length 1.3
  Top Layer w0.4: U2.5 C18.2
NetC22_1: C22.1 R1.2 R2.1 U2.4 | length 6
  Top Layer w0.3: R1.2 R2.1 C22.1 43.899,13.85 43.899,17.15 44.099,17.35 U2.4
NetL2_1: L2.1 U1.27 | length 1.6
  Top Layer w0.3: U1.27 31,19.3 L2.1
NetR6_1: R6.1 R8.2 U3.1 | length 2.6
  Top Layer w0.2: R8.2 R6.1 10.239,33.94 U3.1
NetR7_1: R7.1 R9.2 U3.2 | length 2.6
  Top Layer w0.2: R7.1 R9.2 10.229,32.67 U3.2
NetR10_2: R10.2 U3.7 | length 1.6
  Top Layer w0.2: U3.7 18.945,32.67 R10.2
NSS: K_SM12xx.7 R13.7 | length 17.1
  Top Layer w0.2: K_SM12xx.7 6.18,14.22 7.2,13.2 16,13.2 v1@16.25,12.95 ; v1(15.6,8.8) 15.7,8.9 R13.7
  Bottom Layer w0.2: v1(15.6,8.8) 15.6,11.4 16.25,12.05 v1(16.25,12.9)
NSS_SX: R13.2 U1.20 | length 15
  Top Layer w0.2: R13.2 19.3,8.9 21.35,10.95 26.55,10.95 28.8,13.2 U1.20
RESET: K_SM12xx.10 R14.2 | length 22.5
  Top Layer w0.2: K_SM12xx.10 2.29,16.76 2.29,17.666 1.4,18.556 1.4,22.57 2.152,23.322 6.178,23.322 8.75,20.75 R14.2
RESET_SX: R14.1 U1.6 | length 9.7
  Top Layer w0.2: R14.1 23.2,20.75 23.638,21.188
  Top Layer w0.25: 23.638,21.188 24.15,21.7 25.705,21.7 26.2,21.205 U1.6
RFMOD_SX: RFMDOD.1 U1.21 | length 4.6
  Top Layer w0.2: U1.21 v1(30.1,15.05)
  Bottom Layer w0.2: v1(30.1,15.05) 30.1,12.35 RFMDOD.1
RXTX: K_SM12xx.13 R13.8 | length 22.4
  Top Layer w0.2: v1(11.6,8.4) 11.65,8.4 11.91,8.14 15.79,8.14 16.05,8.4 R13.8
  Bottom Layer w0.2: K_SM12xx.13 4.95,21.75 8.674,18.026 10.574,18.026 11.3,17.3 11.3,8.7 v1(11.6,8.4)
RXTX_SX: R1.1 R13.1 U1.23 | length 30.3
  Top Layer w0.2: R13.1 19.5,8.4 21.6,10.5 26.75,10.5 29.25,13 31.1,13 ; U1.23 30.68,16.7 31.1,16.28 31.1,13 ; R1.1 41.35,13 31.1,13
SCK: K_SM12xx.1 R5.7 | length 17.7
  Top Layer w0.2: K_SM12xx.1 4.95,7.55 8.8,11.4 8.8,12.071 9.429,12.7 15.45,12.7 v1(15.5,12.65) ; v1(15.5,14.7) 15.5,15.05 16.05,15.6 R5.7
  Bottom Layer w0.2: v1(15.5,12.65) v1(15.5,14.7)
SCK_SX: R5.2 U1.17 | length 13.1
  Top Layer w0.2: R5.2 17.8,15.6 21.1,12.3 26.05,12.3 26.85,13.1 U1.17
SCL: K_SM12xx.23 R11.1 U3.6 | length 26.3
  Top Layer w0.2: v1(14.5,27.3) 14.95,27.3 16.5,28.85 16.5,30.844 17.056,31.4 U3.6 18.8,31.4 R11.1
  Bottom Layer w0.2: K_SM12xx.23 14.4,10.97 14.4,27.2 v1(14.5,27.3)
SDA: K_SM12xx.21 R12.1 U3.5 | length 27.1
  Top Layer w0.2: v1(15.1,26.75) 17.349,28.999 U3.5 18.787,30.13 R12.1 ; R12.1@18.865,30.13 R12.1@18.885,30.15
  Bottom Layer w0.2: K_SM12xx.21 14.95,8.98 14.95,26.6 v1(15.1,26.75)
SX_GPIO0: K_SM12xx.25
SX_GPIO1: K_SM12xx.26
SX_GPIO2: K_SM12xx.27
SX_GPIO3: K_SM12xx.28
SX_GPIO4: K_SM12xx.29
SX_GPIO5: K_SM12xx.30
SX_GPIO6: K_SM12xx.31
SX_GPIO7: K_SM12xx.33
VDD_ANA: C6.2 C17.2 C24.2 K_SM12xx.22 R6.2 R7.2 R11.2 R12.2 U2.6 U3.3 U3.8 | length 116.2
  Top Layer w0.3: 7.75,31.65 7.75,31.2 8,30.95 10.9,30.95 11.35,31.4 U3.3
  Top Layer w0.4: R7.2 7.75,31.65 v1(7.75,33.9) R6.2 ; U3.8 18.939,33.94 C6.2 v3(19.85,33.95) 21.4,33.95 ; R12.2 20.007,31.293 R11.2 20.75,31.3 21.4,31.95 21.4,33.95 ; U2.6 44.25,19.5 45,20.25 45,29.75 40.8,33.95 21.4,33.95
  Top Layer w0.8: v3(3.85,4.1) 5.6,4.1 7.25,2.45 C24.2 ; K_SM12xx.22 K_SM12xx.22@10.049,6.581
  Top Layer w1: C24.2 K_SM12xx.22@10.049,6.581
  Bottom Layer w0.6: v3(3.85,4.1) 3.8,4.15 2.2,4.15 0.6,5.75 0.6,30.15 4.35,33.9 v1(7.75,33.9) 10.482,33.9 11.482,34.9 17.367,34.9 18.317,33.95 v3(19.85,33.95)
VDD_FEM: C25.1 K_SM12xx.34 | length 4.1
  Top Layer w0.6: K_SM12xx.34 K_SM12xx.34@10.049,21.859
  Top Layer w1: K_SM12xx.34@10.049,21.859 C25.1
VDD_RF: C23.2 K_SM12xx.2 R3.2 VDD_RFS.1 | length 26.7
  Top Layer w1: C23.2@2.399,2.75 C23.2 2.399,1.451 3.05,0.8 18.75,0.8 VDD_RFS.1 20.8,2.85 R3.2 ; C23.2@2.41,2.761 K_SM12xx.2
VDD_RFS: C3.2 C21.2 C26.2 R3.1 U1.1 U1.15 VDD_RFS.2 | length 61.4
  Top Layer w0.4: C3.2@30.342,22 C3.2
  Top Layer w0.5: U1.1@29.45,20.75 29.45,21.108 C3.2@30.342,22
  Top Layer w0.6: C21.2@25.55,13.9 U1.15@25.55,15.15
  Top Layer w0.65: v3(25.55,13.05) C21.2@25.55,13.9
  Top Layer w0.8: C3.2@30.5,22.05 v3(30.5,28.15)
  Top Layer w1: R3.1 22.6,2.89 VDD_RFS.2 v3(26.15,2.5)
  Bottom Layer w0.8: v3(25.55,13.05) 25.55,7.3 23.25,7.3 18.9,11.65 18.9,24.4 23.4,28.9 29.778,28.9 30.5,28.178 v3(30.5,28.15)
  Bottom Layer w1: 25.55,7.3 25.55,3.1 v3(26.15,2.5)
pads on no net: K_SM12xx.15 R5.1 R5.8 U1.24

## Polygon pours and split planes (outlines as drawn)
GND on Bottom Layer "GND Bottom" (solid, remove dead copper, pour order 7): 0.3,0.3 55.645,0.3 55.7,0.3 55.7,35.7 0.3,35.7
GND on Top Layer "GND Top" (solid, remove dead copper, pour order 6): 0.3,0.3 55.7,0.3 55.7,35.7 0.3,35.7

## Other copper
Top Layer:
  pour cut-out: 51.62,17.515 44.845,17.515 44.815,17.485 44.81,17.49 44.81,17.535 44.83,17.555 51.57,17.555
  region net NetC16_1: 41.58,17.375 41.625,17.375 41.8,17.55 42.775,17.55 42.775,17.15 42.14,17.15 41.715,16.725 41.58,16.725
  region net GND: 24.3,0.3 26.1,0.3 26.1,0.6 24.3,0.6
  region net GND: 35.9,16.551 35.9,16.1 36,16.1 36,16.551
  region net GND: 37.1,16.4 37.1,15.25 37.75,15.25 37.75,16.4
  region net GND: 35.55,16.325 35.55,15.375 35.8,15.375 35.8,16.325
  pour cut-out: 25.091,14.375 25.091,15.459 24.806,15.744 24.65,15.744 24.65,15.845 24.87,15.845 25.226,15.49 25.226,14.415 25.185,14.375
  pour cut-out: 30.083,15.815 30.892,15.815 30.892,15.366 29.864,15.366 29.813,15.417 29.813,15.731
  region net NetC18_2: 45.095,18.325 44.885,18.115 44.88,18.115 44.88,17.89 45.095,17.675 45.238,17.675 45.238,18.323 45.24,18.325
  pour cut-out: 51.61,18.484 44.78,18.484 44.78,18.45 51.629,18.45
  pour cut-out: 36.984,17.535 31.91,17.534 31.901,17.525 31.926,17.5 37.065,17.5 37.03,17.523
  pour cut-out: 34.384,20.534 38.689,20.535 38.501,20.51 34.384,20.51
  pour cut-out: 37.877,16.566 41.766,16.566 41.775,16.575 41.775,16.601 39.251,16.601 37.81,16.61 37.82,16.6 37.85,16.58
  pour cut-out: 37.925,17.535 41.426,17.534 41.43,17.53 41.41,17.51 41.41,17.5 37.885,17.5 37.851,17.515
  region net GND: 38.048,21.895 42.978,21.895 42.988,21.575 38.052,21.575
  region net GND: 46.443,17.516 51.563,17.516 51.653,17.351 51.653,17.191 46.443,17.191
  region net GND: 34.05,16.575 36.55,16.575 36.55,16.25 34.05,16.25
  region net GND: 31.36,15.325 31.36,16.575 33.15,16.575 33.15,16.25 31.746,16.245 31.705,16.204 31.705,15.325
  region net GND: 32.7,19.575 41.766,19.575 41.766,19.25 32.7,19.25
  pour cut-out: 23.516,19.325 23.55,19.325 23.952,19.727 23.952,20.45 24.752,20.45 25.148,20.85 25.152,21.415 25.499,21.415 25.502,20.275 24.702,19.475 23.827,19.475
Bottom Layer:
  region net GND: 25.275,20.2 25.275,15.75 29.725,15.75 29.725,20.2

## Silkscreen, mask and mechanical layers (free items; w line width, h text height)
Top Overlay:
  lines w0.15: 41.8,16.45 41.8,14.4 23.55,14.4 23.55,27.5 27.85,27.5 27.85,24.1 41.8,24.1 41.8,21.7
  text "SX1272RF1" at 47.75,13.95 h1.5 r270
  text "Reference Design" at 26.25,12.7 h0.95
Bottom Overlay:
  text "PCB_E243V03A 0413" at 23.05,10.45 h1 r270
Mechanical 2:
  lines w0.05: 0,0 0,36 56,36 56,0 0,0
  lines w0.1: 36.45,16.5 38.5,16.5 38.5,17.6 36.45,17.6 36.45,16.5
Mechanical 3:
  lines w0.05: 4.15,6.6 5.75,6.6 ; 4.95,5.8 4.95,7.4 ; 0,0 56,0 56,36 0,36 0,0
  text "Origin(0;0)" at -10.35,-1.5 h1
Mechanical 14:
  the board outline again, w0.05
Mechanical 15:
  lines w0.1: 39.517,16.7 38.3,16.7 38.3,17.4 39.517,17.4 ; 35.85,15.35 39.517,15.35 39.517,18.75 35.85,18.75 35.85,15.35 ; 35.85,16.7 35.85,17.4 37.5,17.4 37.5,16.7 35.85,16.7

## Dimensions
0,0 to 0,36 on Mechanical 3
0,0 to 4.95,6.6 on Mechanical 3
0,-0.05 to 4.95,6.6 on Mechanical 3
0,0 to 56,0 on Mechanical 3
